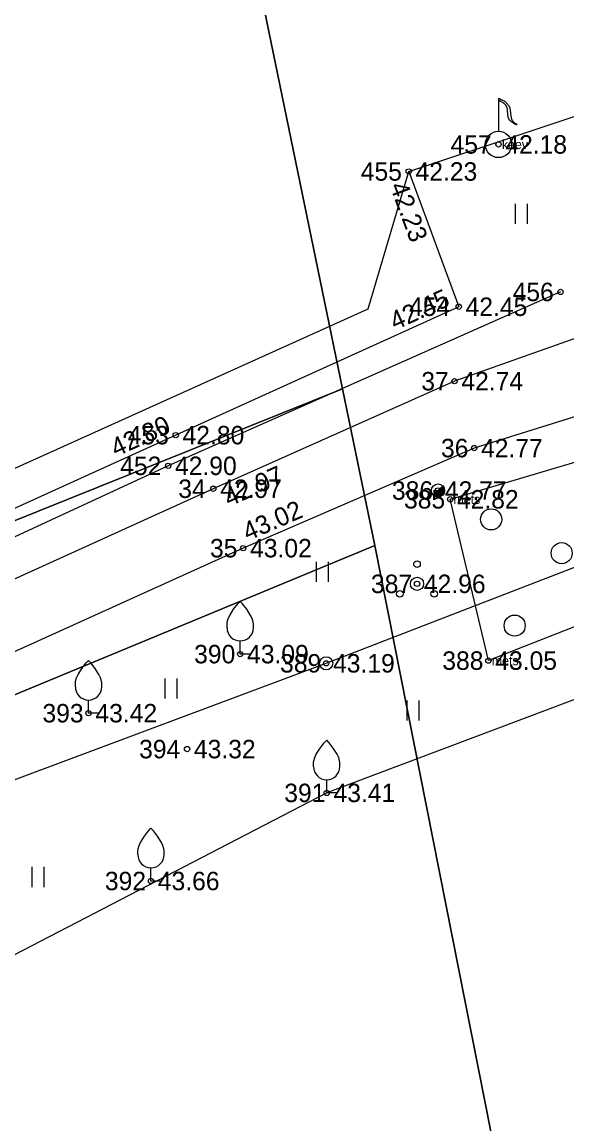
# Model space of a CAD drawing. Extents: x 505800 to 507326, y 6540058 to 6542128.
# Drawn here: x 506068.35 to 506089.04, y 6540204 to 6540245.78 of the extents above; entities that cross this region are included whole.
import ezdxf

# ---------------------------------------------------------------- set-up
doc = ezdxf.new("R2010")
doc.units = 0
for name, color, linetype in [('AED', 7, 'Continuous'), ('HALJASTUS', 7, 'Continuous'), ('KORGUS-EH2000', 7, 'Continuous'), ('MAAMUDEL', 7, 'Continuous'), ('MOOTKORG-EH2000', 7, 'Continuous'), ('MOOTMPUNKT', 7, 'Continuous'), ('MOOTNR', 7, 'Continuous'), ('MOOTPIIR', 7, 'Continuous'), ('MPOHULIIN', 7, 'Continuous'), ('PIIR', 7, 'Continuous'), ('POST', 7, 'Continuous'), ('PUU', 7, 'Continuous'), ('TEE', 7, 'Continuous'), ('VKAEV', 7, 'Continuous')]:
    doc.layers.add(name, color=color, linetype=linetype)

msp = doc.modelspace()

# ---------------------------------------------------------------- linework, layer by layer
at = {"layer": 'AED'}
msp.add_lwpolyline([(506083.03, 6540240.114), (506084.929, 6540234.985), (506074.186, 6540230.116), (506061.873, 6540224.528), (506050.695, 6540219.468), (506044.19, 6540217.171), (506026.923, 6540211.168)], dxfattribs=at)
at = {"layer": 'HALJASTUS'}
for p, q in [((506087.076, 6540238.889), (506087.076, 6540238.128)), ((506087.531, 6540238.889), (506087.531, 6540238.128)), ((506079.52, 6540225.309), (506079.52, 6540224.548)), ((506079.975, 6540225.309), (506079.975, 6540224.548)), ((506073.775, 6540220.893), (506073.775, 6540220.131)), ((506074.23, 6540220.893), (506074.23, 6540220.131)), ((506082.953, 6540220.051), (506082.953, 6540219.29)), ((506083.408, 6540220.051), (506083.408, 6540219.29)), ((506068.73, 6540213.742), (506068.73, 6540212.981)), ((506069.185, 6540213.742), (506069.185, 6540212.981))]:
    msp.add_line(p, q, dxfattribs=at)
for points in [[(506088.794, 6540235.545), (506073.899, 6540228.953), (506064.976, 6540224.831)], [(506091.221, 6540223.598), (506086.055, 6540221.567), (506084.601, 6540227.684), (506090.863, 6540229.542), (506092.12, 6540226.107), (506091.221, 6540223.598)]]:
    msp.add_lwpolyline(points, dxfattribs=at)
for centre in [(506086.16, 6540226.923), (506088.836, 6540225.641), (506087.052, 6540222.894)]:
    msp.add_circle(centre, 0.4, dxfattribs=at)
at = {"layer": 'KORGUS-EH2000'}
for centre in [(506086.438, 6540241.139), (506083.03, 6540240.114), (506088.794, 6540235.545), (506084.929, 6540234.985), (506084.768, 6540232.16), (506074.186, 6540230.116), (506085.515, 6540229.625), (506073.899, 6540228.953), (506075.613, 6540228.084), (506084.143, 6540228.017), (506084.601, 6540227.684), (506076.748, 6540225.83), (506083.346, 6540224.477), (506076.635, 6540221.813), (506079.898, 6540221.464), (506086.055, 6540221.567), (506070.878, 6540219.573), (506074.617, 6540218.212), (506079.917, 6540216.55), (506073.247, 6540213.21)]:
    msp.add_circle(centre, 0.1, dxfattribs=at)
at = {"layer": 'MOOTMPUNKT'}
for centre in [(506086.438, 6540241.139), (506083.03, 6540240.114), (506088.794, 6540235.545), (506084.929, 6540234.985), (506084.768, 6540232.16), (506074.186, 6540230.116), (506085.515, 6540229.625), (506073.899, 6540228.953), (506075.613, 6540228.084), (506084.143, 6540228.017), (506084.601, 6540227.684), (506076.748, 6540225.83), (506083.346, 6540224.477), (506076.635, 6540221.813), (506079.898, 6540221.464), (506086.055, 6540221.567), (506070.878, 6540219.573), (506074.617, 6540218.212), (506079.917, 6540216.55), (506073.247, 6540213.21)]:
    msp.add_circle(centre, 0.1, dxfattribs=at)
at = {"layer": 'MOOTPIIR'}
msp.add_lwpolyline([(506098.399, 6540223.506), (506079.917, 6540216.55), (506066.66, 6540209.695), (506043.081, 6540200.619), (506022.167, 6540189.594), (506009.976, 6540186.473), (506006.85, 6540199.643), (506004.777, 6540209.051), (506007.93, 6540210.81), (506012.129, 6540212.088), (506014.395, 6540212.969), (506023.481, 6540210.643), (506053.328, 6540222.211), (506081.494, 6540234.9), (506083.03, 6540240.114), (506097.119, 6540244.795)], dxfattribs=at)
at = {"layer": 'MPOHULIIN'}
msp.add_lwpolyline([(506023.288, 6540193.167), (506046.819, 6540209.126), (506079.898, 6540221.464), (506112.189, 6540233.927), (506117.49, 6540230.51)], dxfattribs=at)
at = {"layer": 'PIIR'}
for points in [[(505974.82, 6540373.27), (505978.55, 6540356.29), (505982.26, 6540340.2), (505984.17, 6540331.95), (505991.66, 6540295.73), (505997.71, 6540274.55), (506002.06, 6540260.07), (506006.14, 6540246.35), (506007.63, 6540236.84), (506016.86, 6540206.3), (506080.52, 6540231.87), (506081.75, 6540225.93), (506053.1, 6540214.07), (506049.36, 6540212.6), (506018.19, 6540200.68), (506024.58, 6540162.72), (506028.99, 6540136.11), (506032.48, 6540120.26), (506023.4, 6540117.76), (505999.74, 6540236.36), (505986.45, 6540288.25), (505981.09, 6540311.85), (505971.84, 6540354.07), (505949.8, 6540450)], [(506028.99, 6540136.11), (506018.19, 6540200.68), (506049.36, 6540212.6), (506053.99, 6540200.79), (506052.51, 6540200.31), (506055.45, 6540190.69), (506062.61, 6540193.04), (506059.62, 6540202.68), (506057.79, 6540202.01), (506053.1, 6540214.07), (506081.75, 6540225.93), (506090.32, 6540182.64), (506150.17, 6540208.02), (506142.88, 6540238.84), (506158.97, 6540240.95), (506187, 6540243.59), (506198.96, 6540244.45), (506208.53, 6540246.07), (506224.13, 6540249.92), (506272.39, 6540267.75)]]:
    msp.add_lwpolyline(points, dxfattribs=at)
for points in [[(506075.94, 6540254.08), (506092.1, 6540260.96), (506133.36, 6540278.52), (506141.06, 6540246.81), (506150.17, 6540208.02), (506090.32, 6540182.64), (506081.75, 6540225.93), (506080.52, 6540231.87)], [(506075.94, 6540254.08), (506080.52, 6540231.87), (506016.86, 6540206.3), (506007.63, 6540236.84)]]:
    msp.add_lwpolyline(points, close=True, dxfattribs=at)
at = {"layer": 'POST'}
msp.add_line((506083.966, 6540227.84), (506084.32, 6540228.194), dxfattribs=at)
for centre in [(506084.143, 6540228.017), (506079.898, 6540221.464)]:
    msp.add_circle(centre, 0.25, dxfattribs=at)
for radius, start, end in [(0.225, 224.8541, 45.0356), (0.2, 224.8427, 45.047), (0.175, 224.8281, 45.0616), (0.15, 224.8087, 45.081), (0.125, 224.7814, 45.1083), (0.1, 224.7406, 45.1491), (0.075, 224.6725, 45.2172), (0.05, 224.5363, 45.3534), (0.025, 224.1278, 45.7619)]:
    msp.add_arc((506084.143, 6540228.017), radius, start, end, dxfattribs=at)
at = {"layer": 'PUU'}
for p, q in [((506076.635, 6540221.813), (506076.635, 6540222.313)), ((506077.035, 6540221.813), (506076.635, 6540221.813)), ((506070.878, 6540219.573), (506070.878, 6540220.073)), ((506071.278, 6540219.573), (506070.878, 6540219.573)), ((506079.917, 6540216.55), (506079.917, 6540217.05)), ((506080.317, 6540216.55), (506079.917, 6540216.55)), ((506073.247, 6540213.21), (506073.247, 6540213.71)), ((506073.648, 6540213.21), (506073.247, 6540213.21))]:
    msp.add_line(p, q, dxfattribs=at)
for points in [[(506076.135, 6540222.813), (506076.135, 6540222.963), (506076.145, 6540223.028), (506076.18, 6540223.158), (506076.24, 6540223.278), (506076.385, 6540223.513), (506076.545, 6540223.718), (506076.635, 6540223.813)], [(506077.135, 6540222.813), (506077.135, 6540222.963), (506077.125, 6540223.028), (506077.09, 6540223.158), (506077.03, 6540223.278), (506076.885, 6540223.513), (506076.725, 6540223.718), (506076.635, 6540223.813)], [(506070.378, 6540220.573), (506070.378, 6540220.723), (506070.388, 6540220.788), (506070.423, 6540220.918), (506070.483, 6540221.038), (506070.628, 6540221.273), (506070.788, 6540221.478), (506070.878, 6540221.573)], [(506071.378, 6540220.573), (506071.378, 6540220.723), (506071.368, 6540220.788), (506071.333, 6540220.918), (506071.273, 6540221.038), (506071.128, 6540221.273), (506070.968, 6540221.478), (506070.878, 6540221.573)], [(506079.417, 6540217.55), (506079.417, 6540217.7), (506079.427, 6540217.765), (506079.462, 6540217.895), (506079.522, 6540218.015), (506079.667, 6540218.25), (506079.827, 6540218.455), (506079.917, 6540218.55)], [(506080.417, 6540217.55), (506080.417, 6540217.7), (506080.407, 6540217.765), (506080.372, 6540217.895), (506080.312, 6540218.015), (506080.167, 6540218.25), (506080.007, 6540218.455), (506079.917, 6540218.55)], [(506072.747, 6540214.21), (506072.747, 6540214.36), (506072.758, 6540214.425), (506072.793, 6540214.555), (506072.853, 6540214.675), (506072.997, 6540214.91), (506073.158, 6540215.115), (506073.247, 6540215.21)], [(506073.747, 6540214.21), (506073.747, 6540214.36), (506073.737, 6540214.425), (506073.703, 6540214.555), (506073.643, 6540214.675), (506073.497, 6540214.91), (506073.338, 6540215.115), (506073.247, 6540215.21)]]:
    msp.add_lwpolyline(points, dxfattribs=at)
for centre, radius in [((506083.346, 6540225.227), 0.125), ((506083.346, 6540224.477), 0.25), ((506082.696, 6540224.102), 0.125), ((506083.996, 6540224.102), 0.125)]:
    msp.add_circle(centre, radius, dxfattribs=at)
for centre in [(506076.635, 6540222.813), (506070.878, 6540220.573), (506079.917, 6540217.55), (506073.247, 6540214.21)]:
    msp.add_arc(centre, 0.5, 180, 0, dxfattribs=at)
at = {"layer": 'TEE'}
for points in [[(506136.149, 6540239.864), (506135.937, 6540240.063), (506132.254, 6540239.999), (506126.638, 6540239.842), (506117.049, 6540238.049), (506105.059, 6540234.886), (506099.56, 6540233.572), (506092.451, 6540231.789), (506085.515, 6540229.625), (506076.748, 6540225.83), (506064.781, 6540220.419), (506053.702, 6540216.033), (506042.573, 6540211.964), (506030.369, 6540207.528), (506023.645, 6540204.818), (506020.115, 6540202.573), (506018.326, 6540200.153), (506016.859, 6540196.696), (506016.712, 6540193.498), (506017.316, 6540188.473)], [(506091.024, 6540234.378), (506084.768, 6540232.16), (506075.613, 6540228.084), (506063.699, 6540222.682), (506052.876, 6540218.34), (506041.76, 6540214.299), (506029.242, 6540209.942), (506022.519, 6540207.387), (506018.387, 6540205.411), (506016.369, 6540204.542), (506014.779, 6540204.825), (506013.879, 6540206.842), (506012.129, 6540212.088)]]:
    msp.add_lwpolyline(points, dxfattribs=at)
at = {"layer": 'VKAEV'}
msp.add_line((506086.438, 6540242.889), (506086.438, 6540241.639), dxfattribs=at)
msp.add_circle((506086.438, 6540241.139), 0.5, dxfattribs=at)
for points, degree in [([(506086.438, 6540242.889), (506086.488, 6540242.867), (506086.538, 6540242.845), (506086.588, 6540242.824), (506086.65, 6540242.797), (506086.7, 6540242.748), (506086.748, 6540242.699), (506086.783, 6540242.663), (506086.812, 6540242.626), (506086.838, 6540242.584), (506086.853, 6540242.56), (506086.868, 6540242.536), (506086.873, 6540242.509), (506086.887, 6540242.436), (506086.887, 6540242.362), (506086.898, 6540242.289), (506086.907, 6540242.232), (506086.915, 6540242.175), (506086.928, 6540242.119), (506086.934, 6540242.093), (506086.95, 6540242.072), (506086.963, 6540242.049), (506087.001, 6540241.98), (506087.168, 6540241.894), (506087.133, 6540241.889), (506087.105, 6540241.885), (506087.014, 6540241.936), (506086.963, 6540241.974), (506086.94, 6540241.991), (506086.915, 6540242.008), (506086.893, 6540242.029), (506086.869, 6540242.051), (506086.848, 6540242.074), (506086.833, 6540242.104), (506086.817, 6540242.134), (506086.807, 6540242.166), (506086.803, 6540242.199), (506086.798, 6540242.245), (506086.793, 6540242.292), (506086.788, 6540242.339), (506086.784, 6540242.38), (506086.782, 6540242.422), (506086.778, 6540242.464), (506086.775, 6540242.495), (506086.765, 6540242.524), (506086.753, 6540242.554), (506086.74, 6540242.587), (506086.723, 6540242.617), (506086.698, 6540242.644), (506086.677, 6540242.667), (506086.654, 6540242.688), (506086.628, 6540242.704), (506086.598, 6540242.722), (506086.568, 6540242.74), (506086.538, 6540242.759)], 3), ([(506086.543, 6540242.759), (506086.508, 6540242.775), (506086.473, 6540242.792), (506086.438, 6540242.809)], 2)]:
    msp.add_open_spline(points, degree=degree, dxfattribs=at)

# ---------------------------------------------------------------- texts
at = {"layer": 'KORGUS-EH2000'}
for s, rotation, p in [(' 42.23', 290.3152, (506082.21, 6540239.811)), (' 42.45', 24.38, (506082.275, 6540233.974)), (' 42.80', 24.4113, (506071.682, 6540229.172)), (' 42.97', 24.0028, (506075.969, 6540227.284)), (' 43.02', 23.4034, (506076.679, 6540225.991))]:
    msp.add_text(s, height=0.7, rotation=rotation, dxfattribs=at).set_placement(p)
for s, p in [(' 42.96', (506083.346, 6540224.127)), (' 43.05', (506086.055, 6540221.217)), (' 43.32', (506074.617, 6540217.862)), (' 43.41', (506079.917, 6540216.2))]:
    msp.add_text(s, height=0.7, dxfattribs=at).set_placement(p)
at = {"layer": 'MAAMUDEL'}
for s, p in [(' kaev', (506086.438, 6540240.964)), (' mets', (506084.601, 6540227.509)), (' mets', (506086.055, 6540221.392))]:
    msp.add_text(s, height=0.35, dxfattribs=at).set_placement(p)
at = {"layer": 'MOOTKORG-EH2000'}
for s, p in [(' 42.18', (506086.438, 6540240.789)), (' 42.23', (506083.03, 6540239.764)), (' 42.45', (506084.929, 6540234.635)), (' 42.74', (506084.768, 6540231.81)), (' 42.80', (506074.186, 6540229.766)), (' 42.77', (506085.515, 6540229.275)), (' 42.90', (506073.899, 6540228.603)), (' 42.97', (506075.613, 6540227.734)), (' 42.77', (506084.143, 6540227.667)), (' 42.82', (506084.601, 6540227.334)), (' 43.02', (506076.748, 6540225.48)), (' 42.96', (506083.346, 6540224.127)), (' 43.09', (506076.635, 6540221.463)), (' 43.19', (506079.898, 6540221.114)), (' 43.05', (506086.055, 6540221.217)), (' 43.42', (506070.878, 6540219.223)), (' 43.32', (506074.617, 6540217.862)), (' 43.41', (506079.917, 6540216.2)), (' 43.66', (506073.247, 6540212.86))]:
    msp.add_text(s, height=0.7, dxfattribs=at).set_placement(p)
at = {"layer": 'MOOTNR'}
for s, p in [('457 ', (506084.618, 6540240.789)), ('455 ', (506081.21, 6540239.764)), ('456 ', (506086.974, 6540235.195)), ('454 ', (506083.039, 6540234.635)), ('37 ', (506083.508, 6540231.81)), ('453 ', (506072.366, 6540229.766)), ('36 ', (506084.255, 6540229.275)), ('452 ', (506072.079, 6540228.603)), ('34 ', (506074.283, 6540227.734)), ('386 ', (506082.393, 6540227.667)), ('385 ', (506082.851, 6540227.334)), ('35 ', (506075.488, 6540225.48)), ('387 ', (506081.596, 6540224.127)), ('390 ', (506074.885, 6540221.463)), ('389 ', (506078.148, 6540221.114)), ('388 ', (506084.305, 6540221.217)), ('393 ', (506069.128, 6540219.223)), ('394 ', (506072.797, 6540217.862)), ('391 ', (506078.307, 6540216.2)), ('392 ', (506071.498, 6540212.86))]:
    msp.add_text(s, height=0.7, dxfattribs=at).set_placement(p)

doc.saveas('drawing.dxf')
